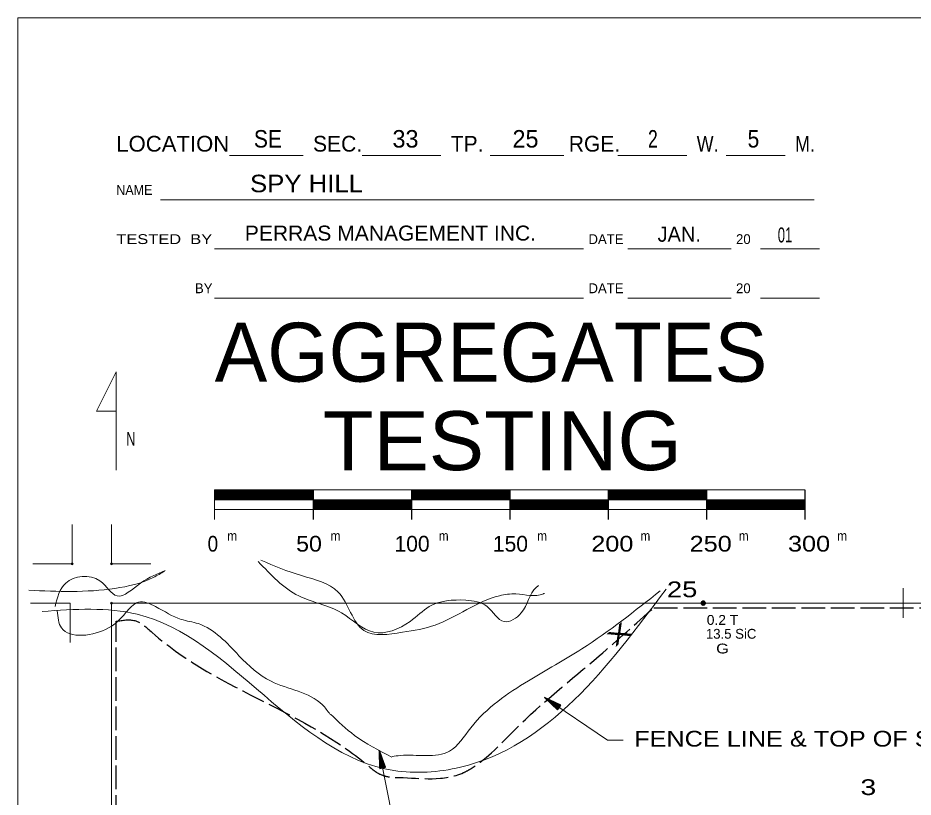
# Model space of a CAD drawing. Extents: x -496 to 480, y -450 to 700.
# Drawn here: x -450 to 5, y 303.7 to 700 of the extents above; entities that cross this region are included whole.
import ezdxf
from ezdxf.enums import TextEntityAlignment as Align

# ---------------------------------------------------------------- set-up
doc = ezdxf.new("R2010")
doc.units = 0
doc.header["$LTSCALE"] = 2
doc.header["$PDMODE"] = 32
doc.header["$PDSIZE"] = 1
doc.linetypes.add('LONG_DASHED', pattern=[7.5, 6, -1.5])
for name, color, linetype, lineweight in [('1', 7, 'Continuous', 13), ('2', 7, 'Continuous', 35), ('3', 7, 'Continuous', 13), ('4', 7, 'Continuous', 25)]:
    doc.layers.add(name, color=color, linetype=linetype, lineweight=lineweight)

msp = doc.modelspace()

# ---------------------------------------------------------------- linework, layer by layer
at = {"layer": '1'}
for p, q in [((-342.517, 629.973), (-305.017, 629.973)), ((-275.017, 629.973), (-235.017, 629.973)), ((-210.017, 629.973), (-172.517, 629.973)), ((-145.017, 629.973), (-110.017, 629.973)), ((-90.017, 629.973), (-60.017, 629.973)), ((-377.517, 607.473), (-45.359, 607.473)), ((-350.017, 582.473), (-162.517, 582.473)), ((-140.017, 582.473), (-87.517, 582.473)), ((-72.517, 582.473), (-42.517, 582.473)), ((-350.017, 557.473), (-162.517, 557.473)), ((-140.017, 557.473), (-87.517, 557.473)), ((-72.517, 557.473), (-42.517, 557.473)), ((-350.017, 459.973), (-350.017, 444.973)), ((-50.017, 459.973), (-350.017, 459.973)), ((-350.017, 454.973), (-50.017, 454.973)), ((-422.391, 422.339), (-422.391, 442.339)), ((-402.391, 422.339), (-402.391, 442.339)), ((-422.391, 422.339), (-442.391, 422.339)), ((-0.017, 394.973), (-0.017, 409.973)), ((-423.537, 402.339), (-443.537, 402.339)), ((-423.537, 402.339), (-423.537, 382.339)), ((-402.391, 402.339), (-402.391, -402.333)), ((-382.391, 402.339), (-402.391, 402.339))]:
    msp.add_line(p, q, dxfattribs=at)
at = {"layer": '1', "lineweight": 25}
for p, q in [((-300.017, 459.973), (-300.017, 444.973)), ((-250.017, 459.973), (-250.017, 444.973)), ((-200.017, 459.973), (-200.017, 444.973)), ((-150.017, 459.973), (-150.017, 444.973)), ((-100.017, 459.973), (-100.017, 444.973)), ((-50.017, 459.973), (-50.017, 444.973)), ((-350.017, 459.473), (-300.017, 459.473)), ((-350.017, 458.973), (-300.017, 458.973)), ((-350.017, 458.473), (-300.017, 458.473)), ((-350.017, 457.973), (-300.017, 457.973)), ((-350.017, 457.473), (-300.017, 457.473)), ((-350.017, 456.973), (-300.017, 456.973)), ((-350.017, 456.473), (-300.017, 456.473)), ((-350.017, 456.473), (-300.017, 456.473)), ((-350.017, 456.473), (-300.017, 456.473)), ((-350.017, 455.973), (-300.017, 455.973)), ((-350.017, 455.973), (-300.017, 455.973)), ((-350.017, 455.473), (-300.017, 455.473)), ((-250.017, 459.473), (-200.017, 459.473)), ((-250.017, 458.973), (-200.017, 458.973)), ((-250.017, 458.473), (-200.017, 458.473)), ((-250.017, 457.973), (-200.017, 457.973)), ((-250.017, 457.473), (-200.017, 457.473)), ((-250.017, 456.973), (-200.017, 456.973)), ((-250.017, 456.473), (-200.017, 456.473)), ((-250.017, 455.973), (-200.017, 455.973)), ((-250.017, 455.473), (-200.017, 455.473)), ((-150.017, 459.473), (-100.017, 459.473)), ((-150.017, 458.973), (-100.017, 458.973)), ((-150.017, 458.473), (-100.017, 458.473)), ((-150.017, 457.973), (-100.017, 457.973)), ((-150.017, 457.473), (-100.017, 457.473)), ((-150.017, 456.973), (-100.017, 456.973)), ((-150.017, 456.473), (-100.017, 456.473)), ((-150.017, 455.973), (-100.017, 455.973)), ((-150.017, 455.473), (-100.017, 455.473)), ((-300.017, 454.473), (-250.017, 454.473)), ((-300.017, 453.973), (-250.017, 453.973)), ((-300.017, 453.473), (-250.017, 453.473)), ((-300.017, 452.973), (-250.017, 452.973)), ((-300.017, 452.473), (-250.017, 452.473)), ((-300.017, 451.973), (-250.017, 451.973)), ((-300.017, 451.473), (-250.017, 451.473)), ((-300.017, 450.973), (-250.017, 450.973)), ((-300.017, 450.473), (-250.017, 450.473)), ((-200.017, 454.473), (-150.017, 454.473)), ((-200.017, 453.973), (-150.017, 453.973)), ((-200.017, 453.473), (-150.017, 453.473)), ((-200.017, 452.973), (-150.017, 452.973)), ((-200.017, 452.473), (-150.017, 452.473)), ((-200.017, 451.973), (-150.017, 451.973)), ((-200.017, 451.473), (-150.017, 451.473)), ((-200.017, 450.973), (-150.017, 450.973)), ((-200.017, 450.473), (-150.017, 450.473)), ((-100.017, 454.473), (-50.017, 454.473)), ((-100.017, 453.973), (-50.017, 453.973)), ((-100.017, 453.473), (-50.017, 453.473)), ((-100.017, 452.973), (-50.017, 452.973)), ((-100.017, 452.473), (-50.017, 452.473)), ((-100.017, 451.973), (-50.017, 451.973)), ((-100.017, 451.473), (-50.017, 451.473)), ((-100.017, 450.973), (-50.017, 450.973)), ((-100.017, 450.473), (-50.017, 450.473))]:
    msp.add_line(p, q, dxfattribs=at)
at = {"layer": '1'}
for points in [[(449.983, -450.027), (449.983, 399.973), (449.983, 699.973), (-450.017, 699.973), (-450.017, 49.973), (-450.017, -450.027)], [(-400.017, 469.973), (-400.017, 519.973), (-410.017, 499.973), (-400.017, 499.973)], [(-350.017, 449.973), (-50.017, 449.973), (-50.017, 459.973)], [(-402.391, 422.339), (-382.391, 422.339), (-402.391, 422.339)], [(402.281, -402.333), (402.281, 402.339), (-402.391, 402.339)]]:
    msp.add_lwpolyline(points, dxfattribs=at)
for p in [(-422.391, 422.339), (-402.391, 422.339), (-402.391, 402.339)]:
    msp.add_point(p, dxfattribs=at)
at = {"layer": '2', "linetype": 'LONG_DASHED', "lineweight": 25}
for p, q in [((-126.758, 400), (287.237, 400)), ((-400, -22.268), (-400, 393.12))]:
    msp.add_line(p, q, dxfattribs=at)
at = {"layer": '2'}
msp.add_circle((-101.678, 402.368), 1, dxfattribs=at)
msp.add_spline([(-101.689, 403.255), (-100.958, 402.851), (-100.807, 402.003), (-101.492, 401.475), (-102.301, 401.705), (-102.587, 402.463), (-102.34, 403.025), (-101.767, 403.193), (-101.093, 402.699), (-101.11, 401.958), (-101.627, 401.699), (-102.149, 401.868), (-102.374, 402.514), (-101.79, 402.98), (-101.352, 402.446), (-101.391, 401.963), (-102.02, 402.098), (-101.874, 402.733), (-101.582, 402.182)], degree=3, dxfattribs=at)
at = {"layer": '2', "linetype": 'LONG_DASHED', "lineweight": 25}
msp.add_spline([(-400, 393.12), (-390.635, 393.471), (-381.839, 387.497), (-324.49, 352.003), (-272.418, 320.023), (-266.085, 315.454), (-261.511, 314.048), (-256.233, 313.697), (-223.513, 316.157), (-219.643, 318.265), (-197.125, 338.297), (-154.553, 375.548), (-126.758, 400.148)], degree=3, dxfattribs=at)
at = {"layer": '3'}
for points in [[(-327.839, 423.521), (-307.214, 406.044), (-285.473, 397.358), (-269.167, 387.586), (-250.688, 393.015), (-240.904, 400.615), (-222.425, 403.873), (-211.554, 400.615), (-202.858, 393.015), (-194.162, 397.358), (-186.552, 410.388), (-185.37, 411.272)], [(-326.48, 424.195), (-305.801, 416.339), (-287.187, 407.972), (-274.158, 388.45), (-254.613, 387.521), (-237.861, 391.239), (-205.286, 406.113), (-196.91, 407.042), (-182.95, 407.042), (-182.289, 407.332)], [(-444.474, 408.902), (-400.731, 409.831), (-381.187, 415.409), (-375.389, 418.619)], [(-431.137, 400.615), (-425.701, 412.559), (-408.309, 413.645), (-399.612, 406.044), (-387.655, 412.559), (-375.091, 418.915)], [(-437.691, 398.136), (-389.319, 396.698), (-258.985, 317.236), (-225.132, 318.927), (-120.574, 409.551)], [(-123.529, 408.654), (-163.307, 379.162), (-190.483, 362.875), (-219.833, 338.988), (-230.703, 327.044), (-255.705, 324.873), (-259.853, 324.321)], [(-291.429, 345.906), (-295.256, 350.67), (-321.345, 362.613), (-337.651, 375.643), (-358.305, 391.929), (-367.001, 394.101), (-380.046, 400.615), (-388.742, 402.787), (-395.264, 397.358), (-403.961, 389.758), (-427.875, 389.758), (-430.05, 398.444)], [(-260.018, 324.102), (-278.881, 335.093), (-291.175, 345.949)]]:
    msp.add_spline(points, degree=3, dxfattribs=at)
at = {"layer": '4', "lineweight": 13}
for points in [[(-142.423, 332.688), (-150.291, 332.688), (-182.42, 354.3)], [(-246.676, 274.4), (-255.855, 274.4), (-266.346, 327.448)]]:
    msp.add_lwpolyline(points, dxfattribs=at)
at = {"layer": '4'}
for points in [[(-182.42, 354.3), (-175.789, 348.032), (-174.115, 350.521)], [(-266.346, 327.448), (-266.072, 318.328), (-263.129, 318.91)]]:
    msp.add_lwpolyline(points, close=True, dxfattribs=at)
for points in [[(-175.801, 348.147), (-182.063, 354.059), (-174.285, 350.487), (-175.755, 348.273), (-181.604, 353.751), (-174.478, 350.462), (-175.799, 348.439), (-181.12, 353.425), (-174.69, 350.408), (-175.789, 348.627), (-180.578, 353.042), (-174.92, 350.387), (-175.834, 348.854), (-179.928, 352.583), (-175.15, 350.307), (-175.859, 349.105), (-179.225, 352.091), (-175.46, 350.222), (-175.922, 349.361), (-178.471, 351.525), (-175.783, 350.205), (-176.015, 349.658), (-177.534, 350.914), (-176.178, 350.14)], [(-265.999, 318.418), (-266.263, 327.026), (-263.273, 319.006), (-265.877, 318.475), (-266.156, 326.484), (-263.427, 319.125), (-265.792, 318.623), (-266.043, 325.912), (-263.616, 319.236), (-265.652, 318.75), (-265.929, 325.258), (-263.794, 319.383), (-265.523, 318.942), (-265.792, 324.474), (-264.013, 319.489), (-265.364, 319.138), (-265.641, 323.629), (-264.292, 319.648), (-265.228, 319.363), (-265.506, 322.696), (-264.534, 319.864), (-265.084, 319.64), (-265.274, 321.601), (-264.859, 320.097)]]:
    msp.add_lwpolyline(points, dxfattribs=at)

# ---------------------------------------------------------------- texts
at = {"layer": '1'}
for s, height, width, p in [('SE', 8.89, 0.9, (-322.943, 634.038)), ('2', 8.89, 0.75, (-127.28, 634.037)), ('5', 8.89, 0.9, (-76.181, 634.038)), ('SPY HILL', 8.89, 1.1, (-303.323, 611.329)), ('PERRAS MANAGEMENT INC.', 7.62, 1.05, (-260.682, 586.728)), ('01', 7.62, 0.65, (-60.119, 585.781))]:
    msp.add_text(s, height=height, dxfattribs=dict(at, width=width)).set_placement(p, align=Align.CENTER)
for s, height, p in [('33', 8.89, (-253.021, 634.038)), ('25', 8.89, (-192.027, 634.038)), ('JAN.', 7.62, (-113.875, 586.148))]:
    msp.add_text(s, height=height, dxfattribs=at).set_placement(p, align=Align.CENTER)
for s, height, width, p in [('LOCATION', 8, 1.05, (-400.017, 631.973)), ('W.', 8, 0.85, (-105.017, 631.973)), ('M.', 8, 0.85, (-55.017, 631.973)), ('NAME', 5, 0.95, (-400.017, 609.973)), ('TESTED  BY', 5, 1.25, (-400.017, 584.973)), ('TESTING', 30, 1.05, (-295.017, 469.973)), ('N', 7, 0.7, (-395.017, 482.473)), ('m', 5, 0.9, (-343.607, 434.073)), ('m', 5, 0.9, (-291.107, 434.073)), ('m', 5, 0.9, (-236.107, 434.073)), ('m', 5, 0.9, (-186.107, 434.073)), ('m', 5, 0.9, (-133.607, 434.073)), ('m', 5, 0.9, (-83.607, 434.073)), ('m', 5, 0.9, (-33.607, 434.073)), ('0', 8, 0.9, (-353.607, 428.573)), ('50', 8, 1.1, (-308.607, 428.573)), ('200', 8, 1.2, (-158.607, 428.573)), ('250', 8, 1.2, (-108.607, 428.573)), ('300', 8, 1.2, (-58.607, 428.573))]:
    msp.add_text(s, height=height, dxfattribs=dict(at, width=width)).set_placement(p)
for s, height, p in [('SEC.', 8, (-300.017, 631.973)), ('TP.', 8, (-230.017, 631.973)), ('RGE.', 8, (-170.017, 631.973)), ('DATE', 5, (-160.017, 584.973)), ('20', 5, (-85.017, 584.973)), ('BY', 5, (-360.017, 559.973)), ('DATE', 5, (-160.017, 559.973)), ('20', 5, (-85.017, 559.973)), ('AGGREGATES', 30, (-350.017, 514.973)), ('100', 8, (-258.607, 428.573)), ('150', 8, (-208.607, 428.573))]:
    msp.add_text(s, height=height, dxfattribs=at).set_placement(p)
at = {"layer": '2'}
for s, width, p in [(' 25', 1.3, (-104.678, 405.368)), ('  3', 1.35, (-13.765, 304.781))]:
    msp.add_text(s, height=8, dxfattribs=dict(at, width=width)).set_placement(p, align=Align.RIGHT)
for s, width, p in [('0.2 T      ', 1.05, (-99.891, 391.328)), ('  G        ', 1.25, (-99.784, 376.777))]:
    msp.add_text(s, height=5, dxfattribs=dict(at, width=width)).set_placement(p)
msp.add_text('13.5 SiC   ', height=5, dxfattribs=at).set_placement((-100.317, 384.265))
at = {"layer": '3', "width": 1.6}
msp.add_text('X', height=8, rotation=38.241, dxfattribs=at).set_placement((-142.006, 383.394), align=Align.CENTER)
at = {"layer": '4', "width": 1.2}
msp.add_text('FENCE LINE & TOP OF SLOPE', height=8, dxfattribs=at).set_placement((-44.072, 329.413), align=Align.CENTER)

doc.saveas('drawing.dxf')
